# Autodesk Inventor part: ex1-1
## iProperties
Shininess: 64.0
Length Units: 11272
Angle Units: 11279
Time Units: 11290
Mass Units: 11286
Length Display Precision: 3
Angle Display Precision: 2
Compacted: True
Part Number: ex1-1
Document SubType Name: Modeling
Created: 2002-09
Designer: Elise Moss
Density: 0.0
Volumn: 0.0
Area: 0.0
PropertySet Name: Model Information
Control State: 0
Master: False
Checked Out: False
Author: Elise Moss
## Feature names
1. Extrusion1
2. Hole1
3. Split1
